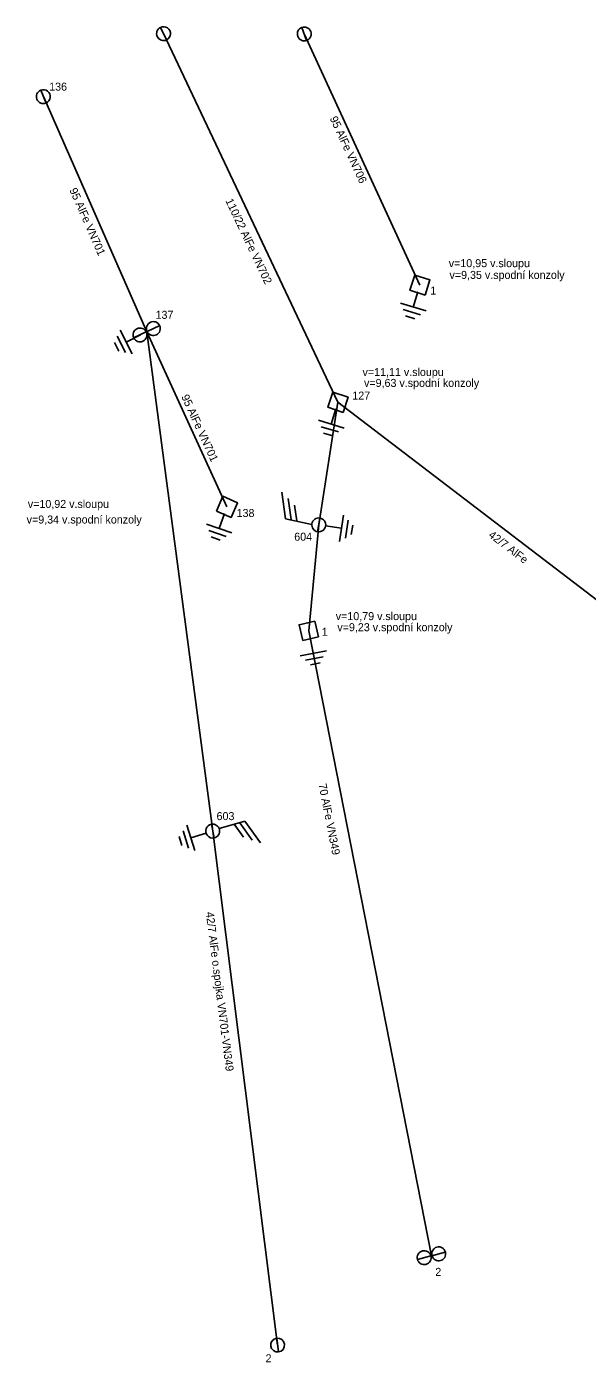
# Model space of a CAD drawing. Extents: x -536386 to -535479, y -1201638 to -1200910.
# Drawn here: x -536256.3 to -536203.8, y -1201365.1 to -1201240 of the extents above; entities that cross this region are included whole.
import ezdxf

# ---------------------------------------------------------------- set-up
doc = ezdxf.new("R2010")
doc.units = 0
for name, color, linetype in [('MAP_ZN_BP', 7, 'Continuous'), ('VÝŠKOPIS', 7, 'Continuous'), ('ZN_BP', 7, 'Continuous')]:
    doc.layers.add(name, color=color, linetype=linetype)

msp = doc.modelspace()

# ---------------------------------------------------------------- linework, layer by layer
at = {"layer": 'MAP_ZN_BP'}
for p, q in [((-536243.19, -1201241.21), (-536243.75, -1201240.03)), ((-536230.06, -1201241.26), (-536230.5, -1201240.04)), ((-536243.47, -1201240.62), (-536227.12, -1201275.16)), ((-536230.28, -1201240.65), (-536219.44, -1201264.18)), ((-536254.48, -1201247.12), (-536254.98, -1201245.92)), ((-536254.73, -1201246.52), (-536245.05, -1201268.55)), ((-536220.06, -1201266.24), (-536219.63, -1201264.8)), ((-536221.26, -1201265.88), (-536218.87, -1201266.6)), ((-536221.02, -1201266.47), (-536219.39, -1201266.96)), ((-536220.78, -1201267.07), (-536219.92, -1201267.33)), ((-536247.53, -1201268.4), (-536246.41, -1201270.63)), ((-536246.97, -1201269.52), (-536245.63, -1201268.84)), ((-536245.1, -1201268.57), (-536246.27, -1201269.13)), ((-536245.05, -1201268.55), (-536237.53, -1201284.96)), ((-536243.83, -1201267.97), (-536245, -1201268.53)), ((-536248.07, -1201269.56), (-536247.66, -1201270.37)), ((-536247.8, -1201268.98), (-536247.04, -1201270.5)), ((-536227.75, -1201277.22), (-536227.31, -1201275.78)), ((-536228.94, -1201276.85), (-536226.55, -1201277.58)), ((-536228.71, -1201277.45), (-536227.08, -1201277.94)), ((-536228.47, -1201278.04), (-536227.61, -1201278.3)), ((-536232.03, -1201286.07), (-536232.37, -1201283.59)), ((-536231.51, -1201286.15), (-536231.79, -1201284.17)), ((-536230.99, -1201286.28), (-536231.2, -1201284.79)), ((-536238.25, -1201286.99), (-536237.75, -1201285.57)), ((-536229.58, -1201286.6), (-536232.03, -1201286.07)), ((-536228.81, -1201286.01), (-536229.03, -1201287.29)), ((-536226.97, -1201288.2), (-536226.61, -1201285.73)), ((-536226.42, -1201287.88), (-536226.17, -1201286.19)), ((-536239.43, -1201286.57), (-536237.07, -1201287.4)), ((-536239.22, -1201287.17), (-536237.61, -1201287.74)), ((-536226.79, -1201286.96), (-536228.28, -1201286.74)), ((-536225.87, -1201287.55), (-536225.74, -1201286.66)), ((-536239, -1201287.78), (-536238.16, -1201288.08)), ((-536229.44, -1201298.68), (-536229.73, -1201297.21)), ((-536230.67, -1201298.92), (-536228.21, -1201298.44)), ((-536230.18, -1201299.33), (-536228.51, -1201299)), ((-536229.69, -1201299.75), (-536228.8, -1201299.57)), ((-536241.28, -1201314.78), (-536240.55, -1201317.17)), ((-536238.74, -1201315.98), (-536238.98, -1201314.7)), ((-536238.25, -1201315.08), (-536235.84, -1201314.41)), ((-536236.86, -1201314.7), (-536235.98, -1201315.92)), ((-536236.33, -1201314.57), (-536235.17, -1201316.2)), ((-536235.84, -1201314.41), (-536234.38, -1201316.44)), ((-536242, -1201315.84), (-536241.74, -1201316.7)), ((-536241.64, -1201315.31), (-536241.14, -1201316.93)), ((-536240.91, -1201315.97), (-536239.48, -1201315.53)), ((-536218.41, -1201355.14), (-536219.66, -1201355.48)), ((-536217.06, -1201354.78), (-536218.31, -1201355.12)), ((-536232.7, -1201364.14), (-536232.86, -1201362.86))]:
    msp.add_line(p, q, dxfattribs=at)
for points in [[(-536218.95, -1201265.12), (-536218.5, -1201263.69), (-536219.93, -1201263.24), (-536220.38, -1201264.67)], [(-536226.65, -1201276.11), (-536226.17, -1201274.69), (-536227.59, -1201274.21), (-536228.07, -1201275.63)], [(-536238.52, -1201285.35), (-536237.14, -1201285.95), (-536236.54, -1201284.57), (-536237.92, -1201283.97)], [(-536230.42, -1201297.47), (-536228.96, -1201297.13), (-536229.3, -1201295.67), (-536230.76, -1201296.01)]]:
    msp.add_lwpolyline(points, close=True, dxfattribs=at)
for points in [[(-536245.05, -1201268.55), (-536238.86, -1201315.34), (-536232.78, -1201363.5)], [(-536227.12, -1201275.16), (-536228.92, -1201286.65), (-536229.86, -1201296.57), (-536218.36, -1201355.13)], [(-536227.12, -1201275.16), (-536199.36, -1201296.36), (-536187.58, -1201305.35), (-536147.73, -1201309.76)]]:
    msp.add_lwpolyline(points, dxfattribs=at)
for centre, start, end in [((-536243.47, -1201240.62), 115.7475, 295.7475), ((-536243.47, -1201240.62), 295.7475, 115.7475), ((-536230.28, -1201240.65), 109.9449, 289.9449), ((-536230.28, -1201240.65), 289.9449, 109.9449), ((-536254.73, -1201246.52), 112.3323, 292.3323), ((-536254.73, -1201246.52), 292.3323, 112.3323), ((-536244.42, -1201268.25), 25.4764, 205.4764), ((-536245.68, -1201268.85), 25.4764, 205.4764), ((-536245.68, -1201268.85), 205.4764, 25.4764), ((-536244.42, -1201268.25), 205.4764, 25.4764), ((-536228.92, -1201286.65), 80.3914, 260.3914), ((-536228.92, -1201286.65), 260.3914, 80.3914), ((-536238.86, -1201315.34), 101.0368, 281.0368), ((-536238.86, -1201315.34), 281.0368, 101.0368), ((-536219.04, -1201355.31), 14.8987, 194.8987), ((-536219.04, -1201355.31), 194.8987, 14.8987), ((-536217.68, -1201354.95), 14.8987, 194.8987), ((-536217.68, -1201354.95), 194.8987, 14.8987), ((-536232.78, -1201363.5), 97.4314, 277.4314), ((-536232.78, -1201363.5), 277.4314, 97.4314)]:
    msp.add_arc(centre, 0.65, start, end, dxfattribs=at)

# ---------------------------------------------------------------- texts
at = {"layer": 'VÝŠKOPIS'}
for s, p in [('v=10,95 v.sloupu', (-536216.74, -1201262.5)), ('v=9,35 v.spodní konzoly', (-536216.67, -1201263.6)), ('v=11,11 v.sloupu', (-536224.82, -1201272.7)), ('v=9,63 v.spodní konzoly', (-536224.68, -1201273.72)), ('v=10,92 v.sloupu', (-536256.19, -1201285.06)), ('v=9,34 v.spodní konzoly', (-536256.3, -1201286.52)), ('v=10,79 v.sloupu', (-536227.33, -1201295.57)), ('v=9,23 v.spodní konzoly', (-536227.18, -1201296.61))]:
    msp.add_text(s, height=0.75, dxfattribs=at).set_placement(p)
at = {"layer": 'ZN_BP'}
for s, p in [('136', (-536254.19, -1201245.96)), ('1', (-536218.47, -1201265.07)), ('137', (-536244.22, -1201267.34)), ('127', (-536225.78, -1201274.91)), ('138', (-536236.62, -1201285.91)), ('604', (-536231.22, -1201288.13)), ('1', (-536228.64, -1201297.04)), ('603', (-536238.5, -1201314.31)), ('2', (-536218, -1201357.01)), ('2', (-536233.91, -1201365.11))]:
    msp.add_text(s, height=0.75, dxfattribs=at).set_placement(p)
for s, rotation, p in [('95 AlFe VN706', 294.735, (-536227.91, -1201248.56)), ('95 AlFe VN701', 293.7207, (-536252.31, -1201255.27)), ('110/22 AlFe VN702', 295.3312, (-536237.69, -1201256.27)), ('95 AlFe VN701', 294.62, (-536241.83, -1201274.63)), ('42/7 AlFe', 322.6314, (-536213.08, -1201287.72)), ('70 AlFe VN349', 281.1103, (-536228.95, -1201310.96)), ('42/7 AlFe o.spojka VN701-VN349', 277.1953, (-536239.51, -1201322.95))]:
    msp.add_text(s, height=0.75, rotation=rotation, dxfattribs=at).set_placement(p)

doc.saveas('drawing.dxf')
